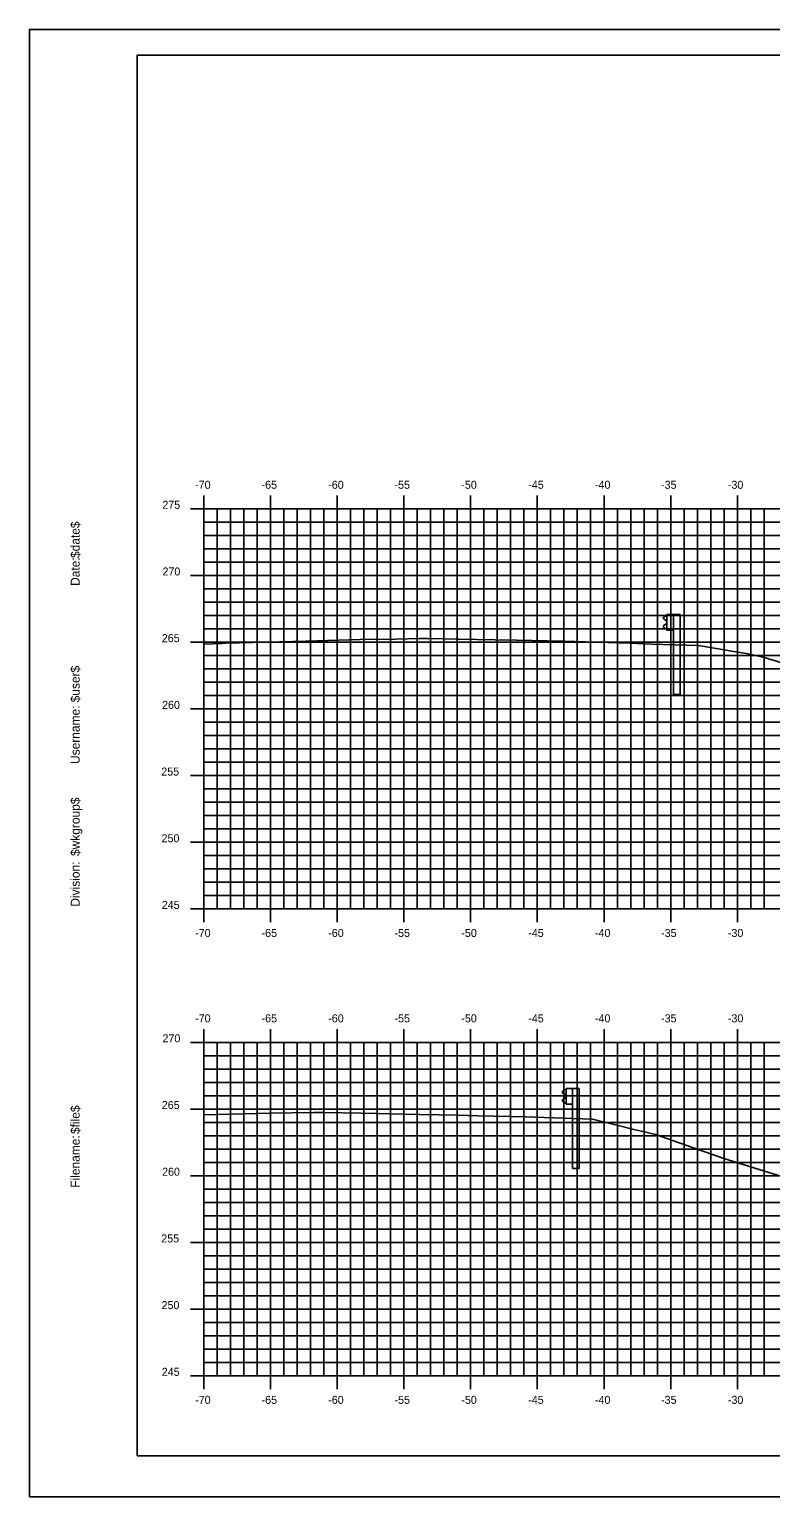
# Model space of a CAD drawing. Extents: x 1168600 to 1177589, y 610178 to 611246.
# Drawn here: x 1175865.5 to 1175921.1, y 610268.7 to 610378.7 of the extents above; entities that cross this region are included whole.
import ezdxf

# ---------------------------------------------------------------- set-up
doc = ezdxf.new("R2010")
doc.units = 0
for name, color, linetype in [('_Construction', 7, 'Continuous'), ('_Station Equation', 7, 'Continuous'), ('D_Slope_Fill', 7, 'Continuous'), ('H_V ANNOTATION', 7, 'Continuous'), ('MAJOR', 7, 'Continuous'), ('MINOR', 7, 'Continuous')]:
    doc.layers.add(name, color=color, linetype=linetype)

msp = doc.modelspace()

# ---------------------------------------------------------------- linework, layer by layer
at = {"layer": '_Construction'}
for p, q in [((1176033.63, 610376.8), (1175873.63, 610376.8)), ((1175873.63, 610376.8), (1175873.63, 610271.8)), ((1175873.63, 610271.8), (1176033.63, 610271.8))]:
    msp.add_line(p, q, dxfattribs=at)
msp.add_lwpolyline([(1175865.54, 610268.74), (1176035.54, 610268.74), (1176035.54, 610378.74), (1175865.54, 610378.74)], close=True, dxfattribs=at)
at = {"layer": '_Station Equation'}
for points in [[(1175878.63, 610332.65), (1175879.96, 610332.71), (1175880.23, 610332.73), (1175880.28, 610332.73), (1175885.29, 610332.86), (1175886.28, 610332.88), (1175890.35, 610332.99), (1175893, 610333.03), (1175894.83, 610333.07), (1175895.15, 610333.07), (1175895.41, 610333.07), (1175897.69, 610333.03), (1175900.47, 610332.98), (1175902.07, 610332.94), (1175905.54, 610332.87), (1175906.44, 610332.84), (1175910.6, 610332.72), (1175912.19, 610332.66), (1175915.71, 610332.54), (1175916.16, 610332.47), (1175918.52, 610332.07), (1175919.31, 610331.94), (1175920.56, 610331.68), (1175922.78, 610330.99)], [(1175878.63, 610297.37), (1175882.54, 610297.46), (1175883.54, 610297.48), (1175886.87, 610297.55), (1175887.13, 610297.54), (1175887.6, 610297.54), (1175890.41, 610297.48), (1175892.66, 610297.44), (1175894.79, 610297.39), (1175897.72, 610297.33), (1175899.17, 610297.29), (1175902.78, 610297.21), (1175903.42, 610297.19), (1175907.77, 610297.04), (1175909.68, 610296.57), (1175910.86, 610296.27), (1175910.98, 610296.24), (1175911.43, 610296.14), (1175912.5, 610295.9), (1175917.61, 610294.1), (1175932.5, 610289.47)]]:
    msp.add_lwpolyline(points, dxfattribs=at)
at = {"layer": 'D_Slope_Fill'}
for p, q in [((1175913.25, 610334.78), (1175913.11, 610334.68)), ((1175913.11, 610334.54), (1175913.3, 610334.4)), ((1175913.3, 610334.18), (1175913.11, 610334.05)), ((1175913.11, 610333.9), (1175913.25, 610333.8)), ((1175913.35, 610334.8), (1175913.27, 610334.79)), ((1175913.34, 610334.34), (1175913.34, 610334.25)), ((1175913.35, 610334.88), (1175913.84, 610334.88)), ((1175913.35, 610333.71), (1175913.35, 610334.88)), ((1175913.84, 610334.88), (1175914.33, 610334.88)), ((1175913.84, 610334.88), (1175913.84, 610333.71)), ((1175914.33, 610334.88), (1175914.33, 610328.88)), ((1175913.27, 610333.8), (1175913.35, 610333.78)), ((1175913.84, 610333.71), (1175913.35, 610333.71)), ((1175913.84, 610328.88), (1175913.84, 610333.71)), ((1175913.84, 610328.88), (1175914.33, 610328.88)), ((1175905.69, 610299.24), (1175905.55, 610299.14)), ((1175905.55, 610299), (1175905.74, 610298.86)), ((1175905.79, 610299.27), (1175905.71, 610299.25)), ((1175905.77, 610298.8), (1175905.77, 610298.71)), ((1175905.79, 610299.34), (1175906.28, 610299.34)), ((1175905.79, 610298.17), (1175905.79, 610299.34)), ((1175906.28, 610299.34), (1175906.77, 610299.34)), ((1175906.28, 610299.34), (1175906.28, 610298.17)), ((1175906.77, 610299.34), (1175906.77, 610293.34)), ((1175905.74, 610298.64), (1175905.55, 610298.51)), ((1175905.55, 610298.37), (1175905.69, 610298.27)), ((1175905.71, 610298.26), (1175905.79, 610298.24)), ((1175906.28, 610298.17), (1175905.79, 610298.17)), ((1175906.28, 610293.34), (1175906.28, 610298.17)), ((1175906.28, 610293.34), (1175906.77, 610293.34))]:
    msp.add_line(p, q, dxfattribs=at)
for centre, major_axis, start_param, end_param in [((1175913.16, 610334.61), (-0.0877, 0), 5.323254, 7.243116), ((1175913.16, 610333.97), (-0.0877, 0), 5.323254, 7.243116), ((1175913.27, 610334.75), (-0.0417, 0), 4.886922, 5.323254), ((1175913.26, 610334.34), (0.0789, 0), 0, 0.959931), ((1175913.26, 610334.25), (0.0789, 0), 5.323254, 6.283185), ((1175913.27, 610333.84), (-0.0417, 0), 0.959931, 1.396263), ((1175905.6, 610299.07), (-0.0877, 0), 5.323254, 7.243116), ((1175905.71, 610299.21), (-0.0417, 0), 4.886922, 5.323254), ((1175905.7, 610298.8), (0.0789, 0), 0, 0.959931), ((1175905.7, 610298.71), (0.0789, 0), 5.323254, 6.283185), ((1175905.6, 610298.44), (-0.0877, 0), 5.323254, 7.243116), ((1175905.71, 610298.3), (-0.0417, 0), 0.959931, 1.396263)]:
    msp.add_ellipse(centre, major_axis=major_axis, ratio=0.995501, start_param=start_param, end_param=end_param, dxfattribs=at)
at = {"layer": 'MAJOR'}
for p, q in [((1175878.63, 610343.8), (1175878.63, 610342.8)), ((1175883.63, 610343.8), (1175883.63, 610342.8)), ((1175888.63, 610343.8), (1175888.63, 610342.8)), ((1175893.63, 610343.8), (1175893.63, 610342.8)), ((1175898.63, 610343.8), (1175898.63, 610342.8)), ((1175903.63, 610343.8), (1175903.63, 610342.8)), ((1175908.63, 610343.8), (1175908.63, 610342.8)), ((1175913.63, 610343.8), (1175913.63, 610342.8)), ((1175918.63, 610343.8), (1175918.63, 610342.8)), ((1175877.63, 610342.8), (1175878.63, 610342.8)), ((1175878.63, 610342.8), (1176018.63, 610342.8)), ((1175878.63, 610312.8), (1175878.63, 610342.8)), ((1175878.63, 610312.8), (1175878.63, 610342.8)), ((1175878.63, 610342.8), (1176018.63, 610342.8)), ((1175883.63, 610312.8), (1175883.63, 610342.8)), ((1175888.63, 610312.8), (1175888.63, 610342.8)), ((1175893.63, 610312.8), (1175893.63, 610342.8)), ((1175898.63, 610312.8), (1175898.63, 610342.8)), ((1175903.63, 610312.8), (1175903.63, 610342.8)), ((1175908.63, 610312.8), (1175908.63, 610342.8)), ((1175913.63, 610312.8), (1175913.63, 610342.8)), ((1175918.63, 610312.8), (1175918.63, 610342.8)), ((1175877.63, 610337.8), (1175878.63, 610337.8)), ((1175878.63, 610337.8), (1176018.63, 610337.8)), ((1175877.63, 610332.8), (1175878.63, 610332.8)), ((1175878.63, 610332.8), (1176018.63, 610332.8)), ((1175877.63, 610327.8), (1175878.63, 610327.8)), ((1175878.63, 610327.8), (1176018.63, 610327.8)), ((1175877.63, 610322.8), (1175878.63, 610322.8)), ((1175878.63, 610322.8), (1176018.63, 610322.8)), ((1175877.63, 610317.8), (1175878.63, 610317.8)), ((1175878.63, 610317.8), (1176018.63, 610317.8)), ((1175877.63, 610312.8), (1175878.63, 610312.8)), ((1175878.63, 610312.8), (1176018.63, 610312.8)), ((1175878.63, 610312.8), (1176018.63, 610312.8)), ((1175878.63, 610311.8), (1175878.63, 610312.8)), ((1175883.63, 610311.8), (1175883.63, 610312.8)), ((1175888.63, 610311.8), (1175888.63, 610312.8)), ((1175893.63, 610311.8), (1175893.63, 610312.8)), ((1175898.63, 610311.8), (1175898.63, 610312.8)), ((1175903.63, 610311.8), (1175903.63, 610312.8)), ((1175908.63, 610311.8), (1175908.63, 610312.8)), ((1175913.63, 610311.8), (1175913.63, 610312.8)), ((1175918.63, 610311.8), (1175918.63, 610312.8)), ((1175878.63, 610303.8), (1175878.63, 610302.8)), ((1175883.63, 610303.8), (1175883.63, 610302.8)), ((1175888.63, 610303.8), (1175888.63, 610302.8)), ((1175893.63, 610303.8), (1175893.63, 610302.8)), ((1175898.63, 610303.8), (1175898.63, 610302.8)), ((1175903.63, 610303.8), (1175903.63, 610302.8)), ((1175908.63, 610303.8), (1175908.63, 610302.8)), ((1175913.63, 610303.8), (1175913.63, 610302.8)), ((1175918.63, 610303.8), (1175918.63, 610302.8)), ((1175877.63, 610302.8), (1175878.63, 610302.8)), ((1175878.63, 610302.8), (1176018.63, 610302.8)), ((1175878.63, 610277.8), (1175878.63, 610302.8)), ((1175878.63, 610277.8), (1175878.63, 610302.8)), ((1175878.63, 610302.8), (1176018.63, 610302.8)), ((1175883.63, 610277.8), (1175883.63, 610302.8)), ((1175888.63, 610277.8), (1175888.63, 610302.8)), ((1175893.63, 610277.8), (1175893.63, 610302.8)), ((1175898.63, 610277.8), (1175898.63, 610302.8)), ((1175903.63, 610277.8), (1175903.63, 610302.8)), ((1175908.63, 610277.8), (1175908.63, 610302.8)), ((1175913.63, 610277.8), (1175913.63, 610302.8)), ((1175918.63, 610277.8), (1175918.63, 610302.8)), ((1175877.63, 610297.8), (1175878.63, 610297.8)), ((1175878.63, 610297.8), (1176018.63, 610297.8)), ((1175877.63, 610292.8), (1175878.63, 610292.8)), ((1175878.63, 610292.8), (1176018.63, 610292.8)), ((1175877.63, 610287.8), (1175878.63, 610287.8)), ((1175878.63, 610287.8), (1176018.63, 610287.8)), ((1175877.63, 610282.8), (1175878.63, 610282.8)), ((1175878.63, 610282.8), (1176018.63, 610282.8)), ((1175877.63, 610277.8), (1175878.63, 610277.8)), ((1175878.63, 610277.8), (1176018.63, 610277.8)), ((1175878.63, 610277.8), (1176018.63, 610277.8)), ((1175878.63, 610276.8), (1175878.63, 610277.8)), ((1175883.63, 610276.8), (1175883.63, 610277.8)), ((1175888.63, 610276.8), (1175888.63, 610277.8)), ((1175893.63, 610276.8), (1175893.63, 610277.8)), ((1175898.63, 610276.8), (1175898.63, 610277.8)), ((1175903.63, 610276.8), (1175903.63, 610277.8)), ((1175908.63, 610276.8), (1175908.63, 610277.8)), ((1175913.63, 610276.8), (1175913.63, 610277.8)), ((1175918.63, 610276.8), (1175918.63, 610277.8))]:
    msp.add_line(p, q, dxfattribs=at)
at = {"layer": 'MINOR'}
for p, q in [((1175879.63, 610312.8), (1175879.63, 610342.8)), ((1175880.63, 610312.8), (1175880.63, 610342.8)), ((1175881.63, 610312.8), (1175881.63, 610342.8)), ((1175882.63, 610312.8), (1175882.63, 610342.8)), ((1175884.63, 610312.8), (1175884.63, 610342.8)), ((1175885.63, 610312.8), (1175885.63, 610342.8)), ((1175886.63, 610312.8), (1175886.63, 610342.8)), ((1175887.63, 610312.8), (1175887.63, 610342.8)), ((1175889.63, 610312.8), (1175889.63, 610342.8)), ((1175890.63, 610312.8), (1175890.63, 610342.8)), ((1175891.63, 610312.8), (1175891.63, 610342.8)), ((1175892.63, 610312.8), (1175892.63, 610342.8)), ((1175894.63, 610312.8), (1175894.63, 610342.8)), ((1175895.63, 610312.8), (1175895.63, 610342.8)), ((1175896.63, 610312.8), (1175896.63, 610342.8)), ((1175897.63, 610312.8), (1175897.63, 610342.8)), ((1175899.63, 610312.8), (1175899.63, 610342.8)), ((1175900.63, 610312.8), (1175900.63, 610342.8)), ((1175901.63, 610312.8), (1175901.63, 610342.8)), ((1175902.63, 610312.8), (1175902.63, 610342.8)), ((1175904.63, 610312.8), (1175904.63, 610342.8)), ((1175905.63, 610312.8), (1175905.63, 610342.8)), ((1175906.63, 610312.8), (1175906.63, 610342.8)), ((1175907.63, 610312.8), (1175907.63, 610342.8)), ((1175909.63, 610312.8), (1175909.63, 610342.8)), ((1175910.63, 610312.8), (1175910.63, 610342.8)), ((1175911.63, 610312.8), (1175911.63, 610342.8)), ((1175912.63, 610312.8), (1175912.63, 610342.8)), ((1175914.63, 610312.8), (1175914.63, 610342.8)), ((1175915.63, 610312.8), (1175915.63, 610342.8)), ((1175916.63, 610312.8), (1175916.63, 610342.8)), ((1175917.63, 610312.8), (1175917.63, 610342.8)), ((1175919.63, 610312.8), (1175919.63, 610342.8)), ((1175920.63, 610312.8), (1175920.63, 610342.8)), ((1175878.63, 610341.8), (1176018.63, 610341.8)), ((1175878.63, 610341.8), (1175879.63, 610341.8)), ((1175878.63, 610340.8), (1176018.63, 610340.8)), ((1175878.63, 610340.8), (1175879.63, 610340.8)), ((1175878.63, 610339.8), (1176018.63, 610339.8)), ((1175878.63, 610339.8), (1175879.63, 610339.8)), ((1175878.63, 610338.8), (1176018.63, 610338.8)), ((1175878.63, 610338.8), (1175879.63, 610338.8)), ((1175878.63, 610336.8), (1176018.63, 610336.8)), ((1175878.63, 610336.8), (1175879.63, 610336.8)), ((1175878.63, 610335.8), (1176018.63, 610335.8)), ((1175878.63, 610335.8), (1175879.63, 610335.8)), ((1175878.63, 610334.8), (1176018.63, 610334.8)), ((1175878.63, 610334.8), (1175879.63, 610334.8)), ((1175878.63, 610333.8), (1176018.63, 610333.8)), ((1175878.63, 610333.8), (1175879.63, 610333.8)), ((1175878.63, 610331.8), (1176018.63, 610331.8)), ((1175878.63, 610331.8), (1175879.63, 610331.8)), ((1175878.63, 610330.8), (1176018.63, 610330.8)), ((1175878.63, 610330.8), (1175879.63, 610330.8)), ((1175878.63, 610329.8), (1176018.63, 610329.8)), ((1175878.63, 610329.8), (1175879.63, 610329.8)), ((1175878.63, 610328.8), (1176018.63, 610328.8)), ((1175878.63, 610328.8), (1175879.63, 610328.8)), ((1175878.63, 610326.8), (1176018.63, 610326.8)), ((1175878.63, 610326.8), (1175879.63, 610326.8)), ((1175878.63, 610325.8), (1176018.63, 610325.8)), ((1175878.63, 610325.8), (1175879.63, 610325.8)), ((1175878.63, 610324.8), (1176018.63, 610324.8)), ((1175878.63, 610324.8), (1175879.63, 610324.8)), ((1175878.63, 610323.8), (1176018.63, 610323.8)), ((1175878.63, 610323.8), (1175879.63, 610323.8)), ((1175878.63, 610321.8), (1176018.63, 610321.8)), ((1175878.63, 610321.8), (1175879.63, 610321.8)), ((1175878.63, 610320.8), (1176018.63, 610320.8)), ((1175878.63, 610320.8), (1175879.63, 610320.8)), ((1175878.63, 610319.8), (1176018.63, 610319.8)), ((1175878.63, 610319.8), (1175879.63, 610319.8)), ((1175878.63, 610318.8), (1176018.63, 610318.8)), ((1175878.63, 610318.8), (1175879.63, 610318.8)), ((1175878.63, 610316.8), (1176018.63, 610316.8)), ((1175878.63, 610316.8), (1175879.63, 610316.8)), ((1175878.63, 610315.8), (1176018.63, 610315.8)), ((1175878.63, 610315.8), (1175879.63, 610315.8)), ((1175878.63, 610314.8), (1176018.63, 610314.8)), ((1175878.63, 610314.8), (1175879.63, 610314.8)), ((1175878.63, 610313.8), (1176018.63, 610313.8)), ((1175878.63, 610313.8), (1175879.63, 610313.8)), ((1175879.63, 610277.8), (1175879.63, 610302.8)), ((1175880.63, 610277.8), (1175880.63, 610302.8)), ((1175881.63, 610277.8), (1175881.63, 610302.8)), ((1175882.63, 610277.8), (1175882.63, 610302.8)), ((1175884.63, 610277.8), (1175884.63, 610302.8)), ((1175885.63, 610277.8), (1175885.63, 610302.8)), ((1175886.63, 610277.8), (1175886.63, 610302.8)), ((1175887.63, 610277.8), (1175887.63, 610302.8)), ((1175889.63, 610277.8), (1175889.63, 610302.8)), ((1175890.63, 610277.8), (1175890.63, 610302.8)), ((1175891.63, 610277.8), (1175891.63, 610302.8)), ((1175892.63, 610277.8), (1175892.63, 610302.8)), ((1175894.63, 610277.8), (1175894.63, 610302.8)), ((1175895.63, 610277.8), (1175895.63, 610302.8)), ((1175896.63, 610277.8), (1175896.63, 610302.8)), ((1175897.63, 610277.8), (1175897.63, 610302.8)), ((1175899.63, 610277.8), (1175899.63, 610302.8)), ((1175900.63, 610277.8), (1175900.63, 610302.8)), ((1175901.63, 610277.8), (1175901.63, 610302.8)), ((1175902.63, 610277.8), (1175902.63, 610302.8)), ((1175904.63, 610277.8), (1175904.63, 610302.8)), ((1175905.63, 610277.8), (1175905.63, 610302.8)), ((1175906.63, 610277.8), (1175906.63, 610302.8)), ((1175907.63, 610277.8), (1175907.63, 610302.8)), ((1175909.63, 610277.8), (1175909.63, 610302.8)), ((1175910.63, 610277.8), (1175910.63, 610302.8)), ((1175911.63, 610277.8), (1175911.63, 610302.8)), ((1175912.63, 610277.8), (1175912.63, 610302.8)), ((1175914.63, 610277.8), (1175914.63, 610302.8)), ((1175915.63, 610277.8), (1175915.63, 610302.8)), ((1175916.63, 610277.8), (1175916.63, 610302.8)), ((1175917.63, 610277.8), (1175917.63, 610302.8)), ((1175919.63, 610277.8), (1175919.63, 610302.8)), ((1175920.63, 610277.8), (1175920.63, 610302.8)), ((1175878.63, 610301.8), (1176018.63, 610301.8)), ((1175878.63, 610301.8), (1175879.63, 610301.8)), ((1175878.63, 610300.8), (1176018.63, 610300.8)), ((1175878.63, 610300.8), (1175879.63, 610300.8)), ((1175878.63, 610299.8), (1176018.63, 610299.8)), ((1175878.63, 610299.8), (1175879.63, 610299.8)), ((1175878.63, 610298.8), (1176018.63, 610298.8)), ((1175878.63, 610298.8), (1175879.63, 610298.8)), ((1175878.63, 610296.8), (1176018.63, 610296.8)), ((1175878.63, 610296.8), (1175879.63, 610296.8)), ((1175878.63, 610295.8), (1176018.63, 610295.8)), ((1175878.63, 610295.8), (1175879.63, 610295.8)), ((1175878.63, 610294.8), (1176018.63, 610294.8)), ((1175878.63, 610294.8), (1175879.63, 610294.8)), ((1175878.63, 610293.8), (1176018.63, 610293.8)), ((1175878.63, 610293.8), (1175879.63, 610293.8)), ((1175878.63, 610291.8), (1176018.63, 610291.8)), ((1175878.63, 610291.8), (1175879.63, 610291.8)), ((1175878.63, 610290.8), (1176018.63, 610290.8)), ((1175878.63, 610290.8), (1175879.63, 610290.8)), ((1175878.63, 610289.8), (1176018.63, 610289.8)), ((1175878.63, 610289.8), (1175879.63, 610289.8)), ((1175878.63, 610288.8), (1176018.63, 610288.8)), ((1175878.63, 610288.8), (1175879.63, 610288.8)), ((1175878.63, 610286.8), (1176018.63, 610286.8)), ((1175878.63, 610286.8), (1175879.63, 610286.8)), ((1175878.63, 610285.8), (1176018.63, 610285.8)), ((1175878.63, 610285.8), (1175879.63, 610285.8)), ((1175878.63, 610284.8), (1176018.63, 610284.8)), ((1175878.63, 610284.8), (1175879.63, 610284.8)), ((1175878.63, 610283.8), (1176018.63, 610283.8)), ((1175878.63, 610283.8), (1175879.63, 610283.8)), ((1175878.63, 610281.8), (1176018.63, 610281.8)), ((1175878.63, 610281.8), (1175879.63, 610281.8)), ((1175878.63, 610280.8), (1176018.63, 610280.8)), ((1175878.63, 610280.8), (1175879.63, 610280.8)), ((1175878.63, 610279.8), (1176018.63, 610279.8)), ((1175878.63, 610279.8), (1175879.63, 610279.8)), ((1175878.63, 610278.8), (1176018.63, 610278.8)), ((1175878.63, 610278.8), (1175879.63, 610278.8))]:
    msp.add_line(p, q, dxfattribs=at)

# ---------------------------------------------------------------- texts
at = {"layer": '_Construction'}
for s, p in [('$date$', (1175869.31, 610339.11)), ('Date:', (1175869.31, 610337.02)), ('$user$', (1175869.31, 610328.29)), ('Username:', (1175869.31, 610323.67)), ('$wkgroup$', (1175869.31, 610316.77)), ('Division:', (1175869.31, 610312.97)), ('$file$', (1175869.31, 610295.93)), ('Filename:', (1175869.31, 610291.9))]:
    msp.add_text(s, height=0.67, rotation=90, dxfattribs=at).set_placement(p)
at = {"layer": 'H_V ANNOTATION'}
for s, p in [('-70', (1175877.97, 610344.3)), ('-65', (1175882.95, 610344.3)), ('-60', (1175887.95, 610344.3)), ('-55', (1175892.92, 610344.3)), ('-50', (1175897.93, 610344.3)), ('-45', (1175902.95, 610344.3)), ('-40', (1175907.95, 610344.3)), ('-35', (1175912.91, 610344.3)), ('-30', (1175917.92, 610344.3)), ('275', (1175875.51, 610342.8)), ('270', (1175875.52, 610337.8)), ('265', (1175875.47, 610332.8)), ('260', (1175875.49, 610327.8)), ('255', (1175875.43, 610322.8)), ('250', (1175875.45, 610317.8)), ('245', (1175875.47, 610312.8)), ('-70', (1175877.97, 610310.7)), ('-65', (1175882.95, 610310.7)), ('-60', (1175887.95, 610310.7)), ('-55', (1175892.92, 610310.7)), ('-50', (1175897.93, 610310.7)), ('-45', (1175902.95, 610310.7)), ('-40', (1175907.95, 610310.7)), ('-35', (1175912.91, 610310.7)), ('-30', (1175917.92, 610310.7)), ('-70', (1175877.97, 610304.3)), ('-65', (1175882.95, 610304.3)), ('-60', (1175887.95, 610304.3)), ('-55', (1175892.92, 610304.3)), ('-50', (1175897.93, 610304.3)), ('-45', (1175902.95, 610304.3)), ('-40', (1175907.95, 610304.3)), ('-35', (1175912.91, 610304.3)), ('-30', (1175917.92, 610304.3)), ('270', (1175875.52, 610302.8)), ('265', (1175875.47, 610297.8)), ('260', (1175875.49, 610292.8)), ('255', (1175875.43, 610287.8)), ('250', (1175875.45, 610282.8)), ('245', (1175875.47, 610277.8)), ('-70', (1175877.97, 610275.7)), ('-65', (1175882.95, 610275.7)), ('-60', (1175887.95, 610275.7)), ('-55', (1175892.92, 610275.7)), ('-50', (1175897.93, 610275.7)), ('-45', (1175902.95, 610275.7)), ('-40', (1175907.95, 610275.7)), ('-35', (1175912.91, 610275.7)), ('-30', (1175917.92, 610275.7))]:
    msp.add_text(s, height=0.6, dxfattribs=at).set_placement(p)

doc.saveas('drawing.dxf')
